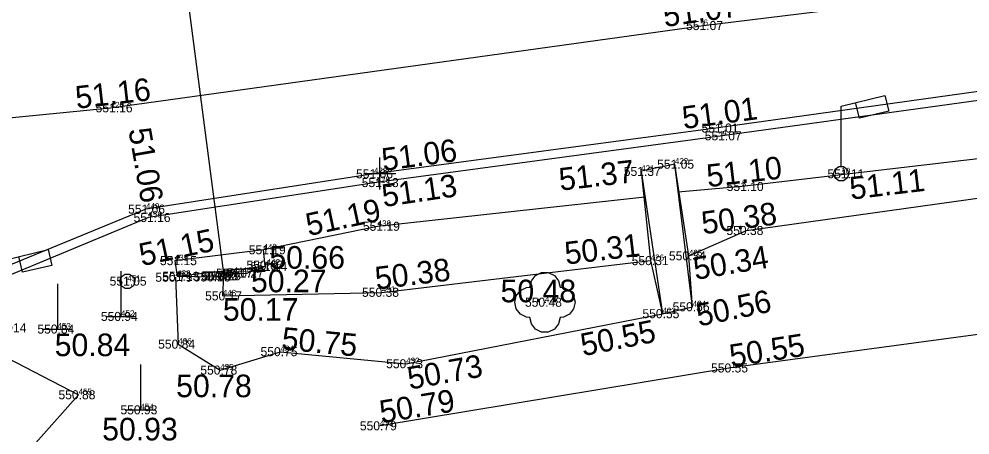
# Model space of a CAD drawing. Extents: x -866693 to -866303, y -1041966 to -1040244.
# Drawn here: x -866661.98 to -866630.41, y -1040308.67 to -1040294.87 of the extents above; entities that cross this region are included whole.
import ezdxf

# ---------------------------------------------------------------- set-up
doc = ezdxf.new("R2010")
doc.units = 0
for name, color, linetype in [('1 hrana zpevněné komunikace-plocha', 7, 'Continuous'), ('10 plot drátěný', 7, 'Continuous'), ('3 osa komunikace', 7, 'Continuous'), ('32 stavba bez rozlišení', 7, 'Continuous'), ('37 propustek', 7, 'Continuous'), ('41 tyčový znak _informační tabule', 7, 'Continuous'), ('43 lampa', 7, 'Continuous'), ('5 obrubník nahoře (chodník)', 7, 'Continuous'), ('51 šoupě-plyn', 7, 'Continuous'), ('54 propustek dno', 7, 'Continuous'), ('60 strom bez rozlišení', 7, 'Continuous'), ('7 hrana svah nahoře', 7, 'Continuous'), ('8 hrana svah dole', 7, 'Continuous'), ('Bod', 7, 'Continuous'), ('Nadmořská výška', 7, 'Continuous'), ('Nadmořská výška_tisk', 7, 'Continuous'), ('Síť křížek', 7, 'Continuous'), ('Číslo bodu', 7, 'Continuous')]:
    doc.layers.add(name, color=color, linetype=linetype)

msp = doc.modelspace()

# ---------------------------------------------------------------- linework, layer by layer
at = {"layer": '1 hrana zpevněné komunikace-plocha'}
msp.add_lwpolyline([(-866503.553, -1040279.722), (-866523.034, -1040282.41), (-866541.374, -1040284.946), (-866561.808, -1040287.782), (-866574.398, -1040289.556), (-866602.398, -1040293.439), (-866619.972, -1040295.863), (-866638.769, -1040298.486), (-866650.196, -1040300.008), (-866657.766, -1040301.183), (-866663.405, -1040303.497), (-866666.7, -1040305.877), (-866670.718, -1040310.555), (-866673.161, -1040315.92), (-866674.075, -1040319.269), (-866673.907, -1040325.701)], dxfattribs=at)
at = {"layer": '10 plot drátěný'}
msp.add_lwpolyline([(-866553.237, -1040304.059), (-866554.808, -1040295.001), (-866574.139, -1040297.591), (-866600.998, -1040301.373), (-866619.297, -1040303.884), (-866638.342, -1040306.448), (-866649.995, -1040308.373)], dxfattribs=at)
at = {"layer": '3 osa komunikace'}
msp.add_lwpolyline([(-866675.016, -1040299.403), (-866658.944, -1040297.823), (-866639.253, -1040295.089), (-866620.168, -1040292.742), (-866603.167, -1040290.212), (-866574.251, -1040285.999), (-866539.891, -1040281.121), (-866503.725, -1040276.174)], dxfattribs=at)
at = {"layer": '32 stavba bez rozlišení'}
msp.add_lwpolyline([(-866641.327, -1040299.925), (-866640.619, -1040304.652), (-866639.614, -1040304.422), (-866640.206, -1040299.685)], close=True, dxfattribs=at)
for points in [[(-866639.614, -1040304.422), (-866639.742, -1040302.731), (-866640.206, -1040299.685)], [(-866641.327, -1040299.925), (-866641.01, -1040302.887), (-866640.619, -1040304.652)]]:
    msp.add_lwpolyline(points, dxfattribs=at)
at = {"layer": '37 propustek'}
msp.add_line((-866656.734, -1040303.41), (-866655.596, -1040303.428), dxfattribs=at)
for points in [[(-866656.734, -1040303.41), (-866653.811, -1040303.076), (-866653.863, -1040302.533), (-866656.813, -1040302.892)], [(-866656.813, -1040302.892), (-866656.734, -1040303.41)], [(-866655.596, -1040303.428), (-866655.177, -1040303.393), (-866654.859, -1040303.312), (-866654.417, -1040303.301), (-866653.811, -1040303.076)]]:
    msp.add_lwpolyline(points, dxfattribs=at)
at = {"layer": '41 tyčový znak _informační tabule'}
for points in [[(-866658.597, -1040303.238), (-866658.597, -1040304.738)], [(-866660.708, -1040303.664), (-866660.708, -1040305.164)], [(-866659.097, -1040304.738), (-866658.097, -1040304.738)], [(-866661.208, -1040305.164), (-866660.208, -1040305.164)], [(-866657.953, -1040306.338), (-866657.953, -1040307.838)], [(-866658.453, -1040307.838), (-866657.453, -1040307.838)]]:
    msp.add_lwpolyline(points, dxfattribs=at)
at = {"layer": '43 lampa'}
for points in [[(-866634.679, -1040299.77), (-866634.604, -1040299.77), (-866634.479, -1040299.86), (-866634.429, -1040300.005), (-866634.479, -1040300.15), (-866634.604, -1040300.24), (-866634.759, -1040300.24), (-866634.884, -1040300.15), (-866634.934, -1040300.005), (-866634.884, -1040299.86), (-866634.759, -1040299.77), (-866634.679, -1040299.77), (-866634.679, -1040297.76), (-866633.229, -1040297.41), (-866633.104, -1040297.935), (-866634.079, -1040298.16), (-866634.204, -1040297.645)], [(-866634.709, -1040300.01), (-866634.649, -1040300.01)], [(-866662.465, -1040304.882), (-866662.39, -1040304.882), (-866662.265, -1040304.972), (-866662.215, -1040305.117), (-866662.265, -1040305.262), (-866662.39, -1040305.352), (-866662.545, -1040305.352), (-866662.67, -1040305.262), (-866662.72, -1040305.117), (-866662.67, -1040304.972), (-866662.545, -1040304.882), (-866662.465, -1040304.882), (-866662.465, -1040302.872), (-866661.015, -1040302.522), (-866660.89, -1040303.047), (-866661.865, -1040303.272), (-866661.99, -1040302.757)]]:
    msp.add_lwpolyline(points, dxfattribs=at)
at = {"layer": '5 obrubník nahoře (chodník)'}
msp.add_lwpolyline([(-866574.644, -1040289.831), (-866602.365, -1040293.689), (-866619.938, -1040296.168), (-866638.627, -1040298.746), (-866650.109, -1040300.299), (-866657.681, -1040301.458), (-866663.286, -1040303.778), (-866664.088, -1040304.254), (-866666.526, -1040306.133), (-866670.469, -1040310.707), (-866672.797, -1040316.126), (-866673.847, -1040319.369), (-866674.075, -1040319.269)], dxfattribs=at)
at = {"layer": '51 šoupě-plyn'}
msp.add_lwpolyline([(-866658.308, -1040303.336), (-866658.183, -1040303.427), (-866658.135, -1040303.574), (-866658.183, -1040303.721), (-866658.308, -1040303.812), (-866658.462, -1040303.812), (-866658.587, -1040303.721), (-866658.635, -1040303.574), (-866658.587, -1040303.427), (-866658.462, -1040303.336)], close=True, dxfattribs=at)
at = {"layer": '54 propustek dno'}
msp.add_line((-866656.784, -1040291.103), (-866655.177, -1040303.393), dxfattribs=at)
at = {"layer": '60 strom bez rozlišení'}
msp.add_lwpolyline([(-866643.518, -1040304.272), (-866643.568, -1040304.489), (-866643.706, -1040304.663), (-866643.907, -1040304.76), (-866644.018, -1040304.772), (-866644.068, -1040304.989), (-866644.206, -1040305.163), (-866644.407, -1040305.26), (-866644.629, -1040305.26), (-866644.829, -1040305.163), (-866644.969, -1040304.989), (-866645.018, -1040304.772), (-866645.129, -1040304.76), (-866645.329, -1040304.663), (-866645.469, -1040304.489), (-866645.518, -1040304.272), (-866645.469, -1040304.055), (-866645.329, -1040303.881), (-866645.129, -1040303.785), (-866645.018, -1040303.772), (-866644.969, -1040303.555), (-866644.829, -1040303.381), (-866644.629, -1040303.285), (-866644.407, -1040303.285), (-866644.206, -1040303.381), (-866644.068, -1040303.555), (-866644.018, -1040303.772), (-866643.907, -1040303.785), (-866643.706, -1040303.881), (-866643.568, -1040304.055)], close=True, dxfattribs=at)
msp.add_lwpolyline([(-866644.543, -1040304.272), (-866644.518, -1040304.272), (-866644.493, -1040304.272)], dxfattribs=at)
at = {"layer": '7 hrana svah nahoře'}
msp.add_line((-866650.074, -1040301.752), (-866653.863, -1040302.533), dxfattribs=at)
for points in [[(-866574.089, -1040291.683), (-866602.145, -1040294.869), (-866619.361, -1040298.247), (-866637.977, -1040300.426), (-866640.09, -1040300.613)], [(-866641.198, -1040300.787), (-866650.074, -1040301.752)], [(-866656.788, -1040303.441), (-866656.695, -1040305.662), (-866655.303, -1040306.519), (-866653.301, -1040305.91), (-866649.127, -1040306.309), (-866640.619, -1040304.652)]]:
    msp.add_lwpolyline(points, dxfattribs=at)
msp.add_lwpolyline([(-866663.286, -1040305.651), (-866660.007, -1040307.34), (-866663.035, -1040310.735), (-866666.071, -1040313.575), (-866667.292, -1040316.164), (-866667.49, -1040317.028), (-866668.573, -1040320.921), (-866669.698, -1040321.759), (-866670.551, -1040321.479), (-866670.968, -1040319.326), (-866670.642, -1040316.567), (-866669.046, -1040311.982)], close=True, dxfattribs=at)
at = {"layer": '8 hrana svah dole'}
msp.add_line((-866655.218, -1040304.059), (-866655.177, -1040303.393), dxfattribs=at)
for points in [[(-866637.829, -1040301.888), (-866619.387, -1040299.311), (-866601.784, -1040296.996), (-866574.214, -1040293.032)], [(-866639.742, -1040302.731), (-866637.829, -1040301.888)], [(-866655.218, -1040304.059), (-866649.933, -1040303.942), (-866641.01, -1040302.887)]]:
    msp.add_lwpolyline(points, dxfattribs=at)
at = {"layer": 'Bod'}
for p, q in [((-866639.253, -1040295.089), (-866639.253, -1040295.089)), ((-866658.944, -1040297.823), (-866658.944, -1040297.823)), ((-866638.769, -1040298.486), (-866638.769, -1040298.486)), ((-866638.627, -1040298.746), (-866638.627, -1040298.746)), ((-866640.206, -1040299.685), (-866640.206, -1040299.685)), ((-866650.196, -1040300.008), (-866650.196, -1040300.008)), ((-866641.327, -1040299.925), (-866641.327, -1040299.925)), ((-866634.679, -1040300.01), (-866634.679, -1040300.01)), ((-866650.109, -1040300.299), (-866650.109, -1040300.299)), ((-866637.977, -1040300.426), (-866637.977, -1040300.426)), ((-866657.766, -1040301.183), (-866657.766, -1040301.183)), ((-866657.681, -1040301.458), (-866657.681, -1040301.458)), ((-866650.074, -1040301.752), (-866650.074, -1040301.752)), ((-866637.829, -1040301.888), (-866637.829, -1040301.888)), ((-866653.863, -1040302.533), (-866653.863, -1040302.533)), ((-866639.742, -1040302.731), (-866639.742, -1040302.731)), ((-866656.813, -1040302.892), (-866656.813, -1040302.892)), ((-866641.01, -1040302.887), (-866641.01, -1040302.887)), ((-866654.859, -1040303.312), (-866654.859, -1040303.312)), ((-866654.417, -1040303.301), (-866654.417, -1040303.301)), ((-866653.811, -1040303.076), (-866653.811, -1040303.076)), ((-866658.385, -1040303.574), (-866658.385, -1040303.574)), ((-866656.788, -1040303.441), (-866656.788, -1040303.441)), ((-866656.734, -1040303.41), (-866656.734, -1040303.41)), ((-866655.596, -1040303.428), (-866655.596, -1040303.428)), ((-866655.261, -1040303.393), (-866655.261, -1040303.393)), ((-866655.177, -1040303.393), (-866655.177, -1040303.393)), ((-866649.933, -1040303.942), (-866649.933, -1040303.942)), ((-866655.218, -1040304.059), (-866655.218, -1040304.059)), ((-866644.518, -1040304.272), (-866644.518, -1040304.272)), ((-866639.614, -1040304.422), (-866639.614, -1040304.422)), ((-866658.597, -1040304.738), (-866658.597, -1040304.738)), ((-866640.619, -1040304.652), (-866640.619, -1040304.652)), ((-866660.708, -1040305.164), (-866660.708, -1040305.164)), ((-866656.695, -1040305.662), (-866656.695, -1040305.662)), ((-866653.301, -1040305.91), (-866653.301, -1040305.91)), ((-866655.303, -1040306.519), (-866655.303, -1040306.519)), ((-866649.127, -1040306.309), (-866649.127, -1040306.309)), ((-866638.342, -1040306.448), (-866638.342, -1040306.448)), ((-866660.007, -1040307.34), (-866660.007, -1040307.34)), ((-866657.953, -1040307.838), (-866657.953, -1040307.838)), ((-866649.995, -1040308.373), (-866649.995, -1040308.373))]:
    msp.add_line(p, q, dxfattribs=at)
at = {"layer": 'Síť křížek'}
for p, q in [((-866650, -1040300.53), (-866650, -1040299.47)), ((-866650.53, -1040300), (-866649.47, -1040300))]:
    msp.add_line(p, q, dxfattribs=at)

# ---------------------------------------------------------------- texts
at = {"layer": 'Nadmořská výška'}
for s, p in [('551.07', (-866639.833, -1040295.24)), ('551.16', (-866659.439, -1040297.97)), ('551.01', (-866639.32, -1040298.64)), ('551.07', (-866639.213, -1040298.9)), ('551.05', (-866640.793, -1040299.84)), ('551.06', (-866650.791, -1040300.16)), ('551.37', (-866641.901, -1040300.08)), ('551.11', (-866635.139, -1040300.16)), ('551.13', (-866650.602, -1040300.45)), ('551.10', (-866638.484, -1040300.58)), ('551.06', (-866658.361, -1040301.33)), ('551.16', (-866658.179, -1040301.61)), ('551.19', (-866650.563, -1040301.9)), ('550.38', (-866638.492, -1040302.04)), ('551.19', (-866654.353, -1040302.68)), ('551.15', (-866657.302, -1040303.04)), ('550.31', (-866641.639, -1040303.04)), ('550.34', (-866640.402, -1040302.88)), ('550.67', (-866654.43, -1040303.19)), ('551.14', (-866654.302, -1040303.23)), ('550.79', (-866657.454, -1040303.59)), ('551.13', (-866657.222, -1040303.56)), ('550.18', (-866656.183, -1040303.58)), ('550.63', (-866655.93, -1040303.54)), ('550.25', (-866655.842, -1040303.54)), ('550.17', (-866655.443, -1040303.46)), ('550.27', (-866655.082, -1040303.45)), ('551.05', (-866658.973, -1040303.72)), ('550.17', (-866655.803, -1040304.21)), ('550.38', (-866650.592, -1040304.09)), ('550.48', (-866645.182, -1040304.42)), ('550.56', (-866640.28, -1040304.57)), ('550.94', (-866659.264, -1040304.89)), ('550.55', (-866641.282, -1040304.8)), ('551.14', (-866662.962, -1040305.27)), ('550.84', (-866661.372, -1040305.31)), ('550.84', (-866657.362, -1040305.81)), ('550.75', (-866653.962, -1040306.06)), ('550.73', (-866649.792, -1040306.46)), ('550.78', (-866655.962, -1040306.67)), ('550.55', (-866639.002, -1040306.6)), ('550.88', (-866660.672, -1040307.49)), ('550.93', (-866658.614, -1040307.99)), ('550.79', (-866650.664, -1040308.52))]:
    msp.add_text(s, height=0.3, dxfattribs=at).set_placement(p)
at = {"layer": 'Nadmořská výška_tisk'}
for s, rotation, p in [('51.07', 8.3189, (-866640.541, -1040295.143)), ('51.16', 6.5586, (-866660.068, -1040297.853)), ('51.01', 7.6411, (-866639.91, -1040298.528)), ('51.06', 279.8895, (-866658.351, -1040298.545)), ('51.06', 7.5429, (-866649.888, -1040299.915)), ('51.37', 6.5623, (-866644.011, -1040300.571)), ('51.10', 6.6816, (-866639.107, -1040300.454)), ('51.11', 6.7408, (-866634.359, -1040300.867)), ('51.13', 8.3781, (-866649.877, -1040301.115)), ('51.19', 12.1239, (-866652.37, -1040302.078)), ('50.38', 7.6534, (-866639.269, -1040302.017)), ('51.15', 12.0077, (-866657.906, -1040303.074)), ('50.31', 6.6931, (-866643.82, -1040303.022)), ('50.34', 9.4488, (-866639.525, -1040303.531)), ('50.38', 6.9842, (-866650.114, -1040303.85)), ('50.56', 11.5804, (-866639.41, -1040305.079)), ('50.55', 11.2021, (-866643.254, -1040306.063)), ('50.75', 354.5931, (-866653.285, -1040305.836)), ('50.55', 8.8458, (-866638.33, -1040306.427)), ('50.73', 10.156, (-866649.012, -1040307.171)), ('50.79', 9.1589, (-866649.947, -1040308.285))]:
    msp.add_text(s, height=0.75, rotation=rotation, dxfattribs=at).set_placement(p)
for s, p in [('50.66', (-866653.668, -1040303.157)), ('50.27', (-866654.28, -1040303.939)), ('50.48', (-866645.992, -1040304.272)), ('50.17', (-866655.213, -1040304.884)), ('50.84', (-866660.797, -1040306.059)), ('50.78', (-866656.764, -1040307.421)), ('50.93', (-866659.221, -1040308.854))]:
    msp.add_text(s, height=0.75, dxfattribs=at).set_placement(p)
at = {"layer": 'Číslo bodu'}
for s, p in [('6', (-866639.253, -1040295.089)), ('420', (-866658.944, -1040297.823)), ('5', (-866638.769, -1040298.486)), ('4', (-866638.627, -1040298.746)), ('422', (-866640.206, -1040299.685)), ('428', (-866650.196, -1040300.008)), ('421', (-866641.327, -1040299.925)), ('10', (-866634.679, -1040300.01)), ('429', (-866650.109, -1040300.299)), ('3', (-866637.977, -1040300.426)), ('449', (-866657.766, -1040301.183)), ('450', (-866657.681, -1040301.458)), ('430', (-866650.074, -1040301.752)), ('2', (-866637.829, -1040301.888)), ('440', (-866653.863, -1040302.533)), ('439', (-866656.813, -1040302.892)), ('426', (-866641.01, -1040302.887)), ('425', (-866639.742, -1040302.731)), ('441', (-866653.811, -1040303.076)), ('442', (-866653.758, -1040303.039)), ('451', (-866658.385, -1040303.574)), ('437', (-866656.788, -1040303.441)), ('438', (-866656.734, -1040303.41)), ('445', (-866655.596, -1040303.428)), ('447', (-866655.261, -1040303.393)), ('446', (-866655.177, -1040303.393)), ('444', (-866654.859, -1040303.312)), ('443', (-866654.417, -1040303.301)), ('448', (-866655.218, -1040304.059)), ('431', (-866649.933, -1040303.942)), ('427', (-866644.518, -1040304.272)), ('424', (-866639.614, -1040304.422)), ('452', (-866658.597, -1040304.738)), ('423', (-866640.619, -1040304.652)), ('453', (-866660.708, -1040305.164)), ('436', (-866656.695, -1040305.662)), ('434', (-866653.301, -1040305.91)), ('432', (-866649.127, -1040306.309)), ('435', (-866655.303, -1040306.519)), ('1', (-866638.342, -1040306.448)), ('455', (-866660.007, -1040307.34)), ('454', (-866657.953, -1040307.838)), ('433', (-866649.995, -1040308.373))]:
    msp.add_text(s, height=0.2, dxfattribs=at).set_placement(p)

doc.saveas('drawing.dxf')
